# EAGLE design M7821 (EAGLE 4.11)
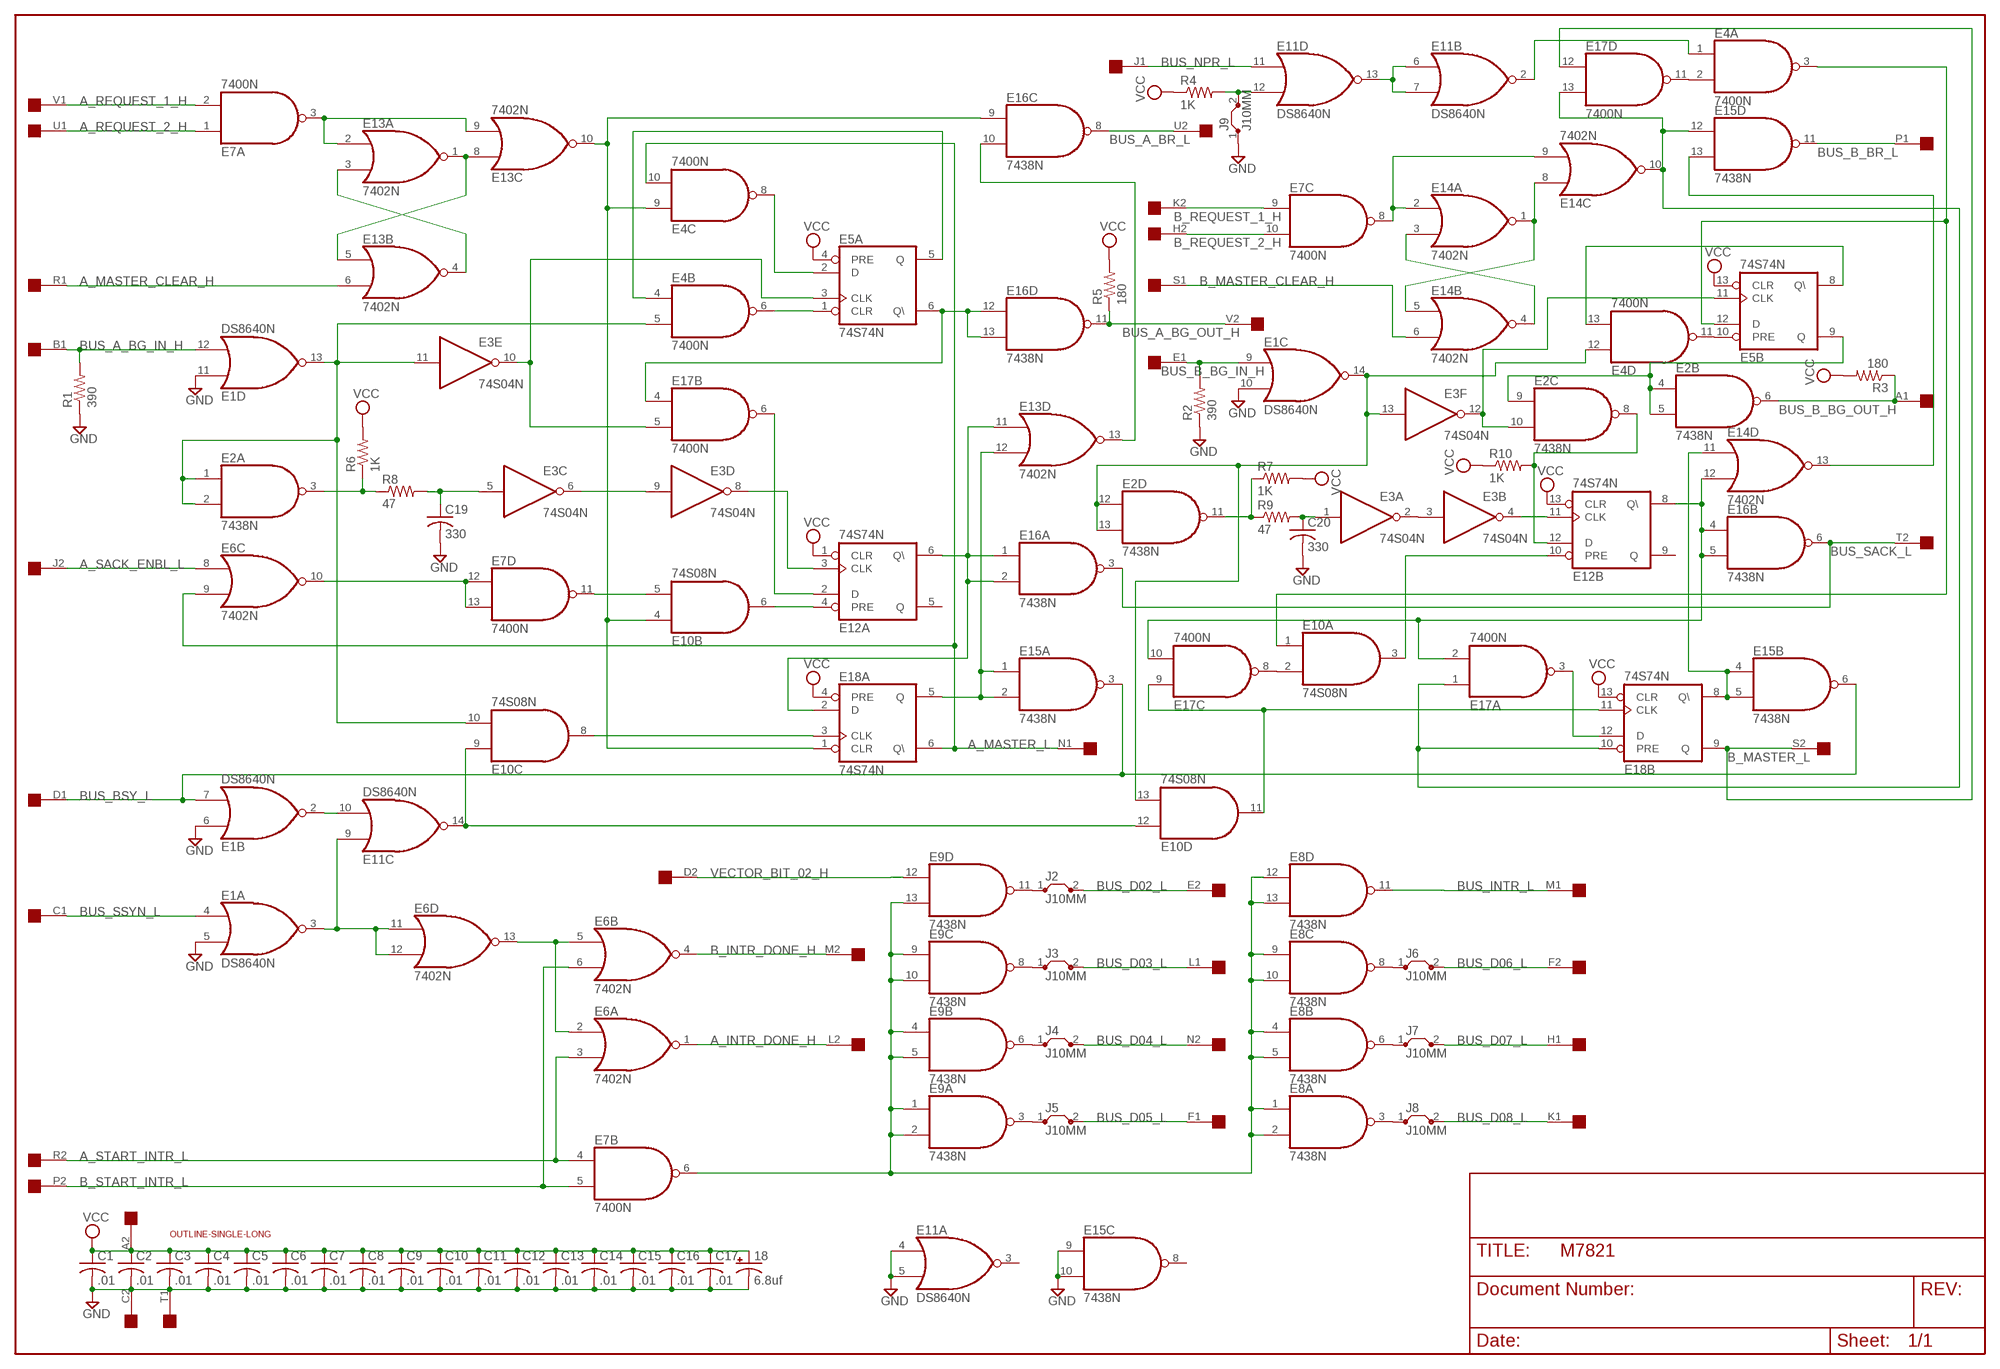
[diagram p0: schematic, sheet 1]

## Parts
18  6.8uf  CPOL-USE15-5AXIAL  [E15-5]
C1  .01  C-US050-025X075  [C050-025X075]
C2  .01  C-US050-025X075  [C050-025X075]
C3  .01  C-US050-025X075  [C050-025X075]
C4  .01  C-US050-025X075  [C050-025X075]
C5  .01  C-US050-025X075  [C050-025X075]
C6  .01  C-US050-025X075  [C050-025X075]
C7  .01  C-US050-025X075  [C050-025X075]
C8  .01  C-US050-025X075  [C050-025X075]
C9  .01  C-US050-025X075  [C050-025X075]
C10  .01  C-US050-025X075  [C050-025X075]
C11  .01  C-US050-025X075  [C050-025X075]
C12  .01  C-US050-025X075  [C050-025X075]
C13  .01  C-US050-025X075  [C050-025X075]
C14  .01  C-US050-025X075  [C050-025X075]
C15  .01  C-US050-025X075  [C050-025X075]
C16  .01  C-US050-025X075  [C050-025X075]
C17  .01  C-US050-025X075  [C050-025X075]
C19  330  C-US050-025X075  [C050-025X075]
C20  330  C-US050-025X075  [C050-025X075]
E1  DS8640N  [DIL14]
E2  7438N  [DIL14]
E3  74S04N  [DIL14]
E4  7400N  [DIL14]
E5  74S74N  [DIL14]
E6  7402N  [DIL14]
E7  7400N  [DIL14]
E8  7438N  [DIL14]
E9  7438N  [DIL14]
E10  74S08N  [DIL14]
E11  DS8640N  [DIL14]
E12  74S74N  [DIL14]
E13  7402N  [DIL14]
E14  7402N  [DIL14]
E15  7438N  [DIL14]
E16  7438N  [DIL14]
E17  7400N  [DIL14]
E18  74S74N  [DIL14]
J2  J10MM  [10]
J3  J10MM  [10]
J4  J10MM  [10]
J5  J10MM  [10]
J6  J10MM  [10]
J7  J10MM  [10]
J8  J10MM  [10]
J9  J10MM  [10]
R1  390  R-US_0207/10  [0207/10]
R2  390  R-US_0207/10  [0207/10]
R3  180  R-US_0207/10  [0207/10]
R4  1K  R-US_0207/10  [0207/10]
R5  180  R-US_0207/10  [0207/10]
R6  1K  R-US_0207/10  [0207/10]
R7  1K  R-US_0207/10  [0207/10]
R8  47  R-US_0207/10  [0207/10]
R9  47  R-US_0207/10  [0207/10]
R10  1K  R-US_0207/10  [0207/10]
U$1  OUTLINE-SINGLE-LONG  [SINGLE-LONG]
U$2  SINGLE  [EDGE-CON2]

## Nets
A_INTR_DONE_H: E6.1(A:O) U$2.L2
A_MASTER_CLEAR_H: E13.6(B:I1) U$2.R1
A_MASTER_L: E4.10(C:I1) E6.9(C:I1) E18.6(A:Q\) U$2.N1
A_REQUEST_1_H: E7.2(A:I1) U$2.V1
A_REQUEST_2_H: E7.1(A:I0) U$2.U1
A_SACK_ENBL_L: E6.8(C:I0) U$2.J2
A_START_INTR_L: E6.3(A:I1) E7.4(B:I0) U$2.R2
B_INTR_DONE_H: E6.4(B:O) U$2.M2
B_MASTER_CLEAR_H: E14.6(B:I1) U$2.S1
B_MASTER_L: E17.12(D:I0) E18.9(B:Q) U$2.S2
B_REQUEST_1_H: E7.9(C:I0) U$2.K2
B_REQUEST_2_H: E7.10(C:I1) U$2.H2
B_START_INTR_L: E6.6(B:I1) E7.5(B:I1) U$2.P2
BUS_A_BG_IN_H: E1.12(D:I1) R1.2 U$2.B1
BUS_A_BG_OUT_H: E16.11(D:O) R5.1 U$2.V2
BUS_A_BR_L: E16.8(C:O) U$2.U2
BUS_B_BG_IN_H: E1.9(C:I0) R2.2 U$2.E1
BUS_B_BG_OUT_H: E2.6(B:O) R3.1 U$2.A1
BUS_B_BR_L: E15.11(D:O) U$2.P1
BUS_BSY_L: E1.7(B:I1) E15.3(A:O) E15.6(B:O) U$2.D1
BUS_D02_L: J2.2 U$2.E2
BUS_D03_L: J3.2 U$2.L1
BUS_D04_L: J4.2 U$2.N2
BUS_D05_L: J5.2 U$2.F1
BUS_D06_L: J6.2 U$2.F2
BUS_D07_L: J7.2 U$2.H1
BUS_D08_L: J8.2 U$2.K1
BUS_INTR_L: E8.11(D:O) U$2.M1
BUS_NPR_L: E11.11(D:I0) U$2.J1
BUS_SACK_L: E16.3(A:O) E16.6(B:O) U$2.T2
BUS_SSYN_L: E1.4(A:I0) U$2.C1
GND: 18.- C1.2 C2.2 C3.2 C4.2 C5.2 C6.2 C7.2 C8.2 C9.2 C10.2 C11.2 C12.2 C13.2 C14.2 C15.2 C16.2 C17.2 C19.2 C20.2 E1.5(A:I1) E1.6(B:I0) E1.10(C:I1) E1.11(D:I0) E11.4(A:I0) E11.5(A:I1) E15.9(C:I0) E15.10(C:I1) J9.1 R1.1 R2.1 U$2.C2 U$2.T1
N$1: E1.14(C:O) E2.12(D:I0) E2.13(D:I1) E3.13(F:I) E4.12(D:I0) E10.13(D:I1)
N$2: E1.13(D:O) E2.1(A:I0) E2.2(A:I1) E3.11(E:I) E4.5(B:I1) E10.10(C:I1)
N$3: E1.3(A:O) E6.11(D:I0) E6.12(D:I1) E11.9(C:I0)
N$4: E1.2(B:O) E11.10(C:I1)
N$5: E7.8(C:O) E14.2(A:I0) E14.9(C:I1)
N$6: E11.12(D:I1) J9.2 R4.2
N$7: E11.6(B:I0) E11.7(B:I1) E11.13(D:O)
N$8: E6.10(C:O) E7.12(D:I0) E7.13(D:I1)
N$9: E14.3(A:I1) E14.4(B:O)
N$10: E9.11(D:O) J2.1
N$11: E3.8(D:O) E12.3(A:CLK)
N$12: E7.11(D:O) E10.5(B:I1)
N$13: E4.13(D:I1) E5.8(B:Q\)
N$14: E14.1(A:O) E14.5(B:I0) E14.8(C:I0)
N$15: E2.11(D:O) R7.1 R9.1
N$16: E9.3(A:O) J5.1
N$17: E9.6(B:O) J4.1
N$18: E9.8(C:O) J3.1
N$19: E10.9(C:I0) E10.12(D:I0) E11.14(C:O)
N$20: E8.3(A:O) J8.1
N$21: E8.6(B:O) J7.1
N$22: E8.8(C:O) J6.1
N$23: E7.6(B:O) E8.1(A:I0) E8.2(A:I1) E8.4(B:I0) E8.5(B:I1) E8.9(C:I0) E8.10(C:I1) E8.12(D:I0) E8.13(D:I1) E9.1(A:I0) E9.2(A:I1) E9.4(B:I0) E9.5(B:I1) E9.9(C:I0) E9.10(C:I1) E9.13(D:I1)
N$24: E12.6(A:Q\) E13.11(D:I0) E16.1(A:I0) E16.2(A:I1) E18.2(A:D)
N$25: E13.12(D:I1) E15.1(A:I0) E15.2(A:I1) E18.5(A:Q)
N$26: E4.6(B:O) E5.1(A:CLR)
N$27: E4.8(C:O) E5.2(A:D)
N$28: E4.4(B:I0) E5.5(A:Q)
N$29: E3.10(E:O) E5.3(A:CLK) E17.5(B:I1)
N$30: E12.2(A:D) E17.6(B:O)
N$31: E5.6(A:Q\) E16.12(D:I0) E16.13(D:I1) E17.4(B:I0)
N$32: E13.13(D:O) E16.10(C:I1)
N$33: C20.1 E3.1(A:I) R9.2
N$34: E6.2(A:I0) E6.5(B:I0) E6.13(D:O)
N$35: E3.2(A:O) E3.3(B:I)
N$36: E3.4(B:O) E12.11(B:CLK)
N$37: E10.6(B:O) E12.4(A:PRE)
N$38: E2.3(A:O) R6.1 R8.1
N$39: C19.1 E3.5(C:I) R8.2
N$40: E3.6(C:O) E3.9(D:I)
N$41: E10.11(D:O) E17.9(C:I0) E18.11(B:CLK)
N$42: E7.3(A:O) E13.2(A:I0) E13.9(C:I1)
N$43: E13.1(A:O) E13.5(B:I0) E13.8(C:I0)
N$44: E13.3(A:I1) E13.4(B:O)
N$45: E4.9(C:I0) E10.4(B:I0) E13.10(C:O) E16.9(C:I0) E18.1(A:CLR)
N$46: E10.8(C:O) E18.3(A:CLK)
N$47: E4.1(A:I0) E11.2(B:O)
N$48: E14.11(D:I0) E15.4(B:I0) E15.5(B:I1) E18.8(B:Q\)
N$49: E17.3(A:O) E18.12(B:D)
N$50: E14.10(C:O) E15.12(D:I0) E17.1(A:I0) E17.13(D:I1) E18.10(B:PRE)
N$51: E10.2(A:I1) E17.8(C:O)
N$52: E12.8(B:Q\) E14.12(D:I1) E16.4(B:I0) E16.5(B:I1) E17.2(A:I1) E17.10(C:I1)
N$53: E10.3(A:O) E12.10(B:PRE)
N$54: E4.3(A:O) E5.12(B:D) E10.1(A:I0)
N$55: E2.8(C:O) E12.12(B:D) R10.2
N$56: E2.10(C:I1) E3.12(F:O) E5.11(B:CLK)
N$57: E2.4(B:I0) E2.5(B:I1) E2.9(C:I0) E5.9(B:Q)
N$58: E4.11(D:O) E5.10(B:PRE)
N$60: E4.2(A:I1) E17.11(D:O)
N$61: E14.13(D:O) E15.13(D:I1)
VCC: 18.+ C1.1 C2.1 C3.1 C4.1 C5.1 C6.1 C7.1 C8.1 C9.1 C10.1 C11.1 C12.1 C13.1 C14.1 C15.1 C16.1 C17.1 E5.4(A:PRE) E5.13(B:CLR) E12.1(A:CLR) E12.13(B:CLR) E18.4(A:PRE) E18.13(B:CLR) R3.2 R4.1 R5.2 R6.2 R7.2 R10.1 U$2.A2
VECTOR_BIT_02_H: E9.12(D:I0) U$2.D2
Unconnected: E11.3(A:O) E12.5(A:Q) E12.9(B:Q) E15.8(C:O) U$2.B2

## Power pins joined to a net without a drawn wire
GND: E1.1(P:GND) E2.7(P:GND) E3.7(P:GND) E4.7(P:GND) E5.7(P:GND) E6.7(P:GND) E7.7(P:GND) E8.7(P:GND) E9.7(P:GND) E10.7(P:GND) E11.1(P:GND) E12.7(P:GND) E13.7(P:GND) E14.7(P:GND) E15.7(P:GND) E16.7(P:GND) E17.7(P:GND) E18.7(P:GND)
VCC: E1.8(P:VCC) E2.14(P:VCC) E3.14(P:VCC) E4.14(P:VCC) E5.14(P:VCC) E6.14(P:VCC) E7.14(P:VCC) E8.14(P:VCC) E9.14(P:VCC) E10.14(P:VCC) E11.8(P:VCC) E12.14(P:VCC) E13.14(P:VCC) E14.14(P:VCC) E15.14(P:VCC) E16.14(P:VCC) E17.14(P:VCC) E18.14(P:VCC)

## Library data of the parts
18 = rcl:CPOL-US: POLARIZED CAPACITOR, American symbol
C1-C17 C19 C20 = rcl:C-US: CAPACITOR, American symbol
E1 E11 = dec-con:DS8640: Quad NOR gate
E2 E8 E9 E15 E16 = 74xx-jameco:74*38: Quad 2-input NAND gate, open collector output
E3 = 74xx-jameco:74*04: Hex INVERTER
E4 E7 E17 = 74xx-jameco:74*00: Quad 2-input NAND gate
E5 E12 E18 = 74xx-jameco:74*74: Dual D type positive edge triggered FLIP FLOP, preset and clear
E6 E14 = 74xx-jameco:74*02: Quad 2-input NOR gate
E10 = 74xx-jameco:74*08: Quad 2-input AND gate
E13 = 74xx-us:74*02: Quad 2-input NOR gate
J2-J9 = jumper:J: Bridge
R1-R10 = rcl:R-US_: RESISTOR, American symbol
U$1 = dec-con:OUTLINE-*: Board outlines for DEC boards.
U$2 = dec-con:SINGLE: Single-Height DEC board

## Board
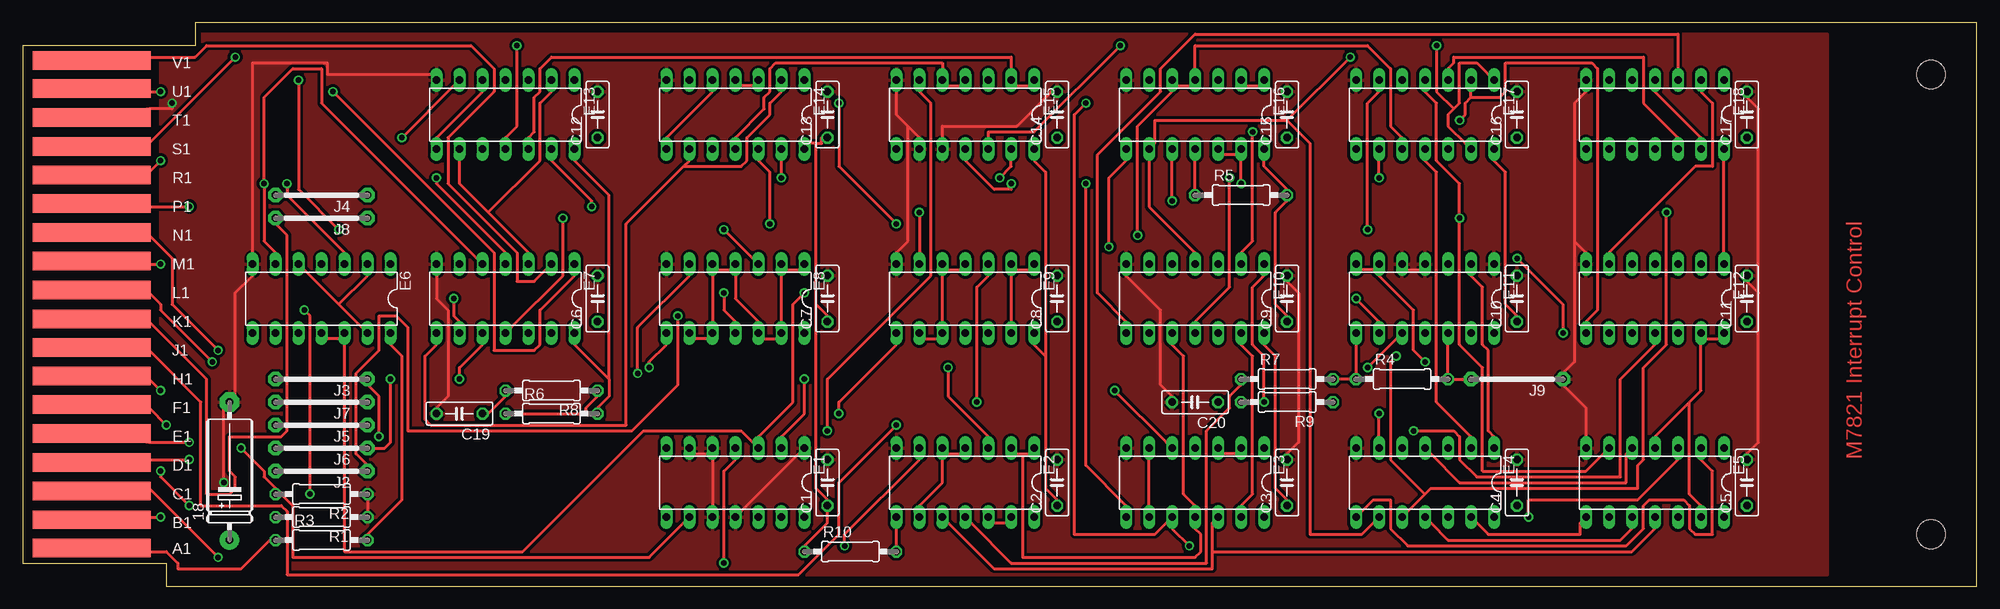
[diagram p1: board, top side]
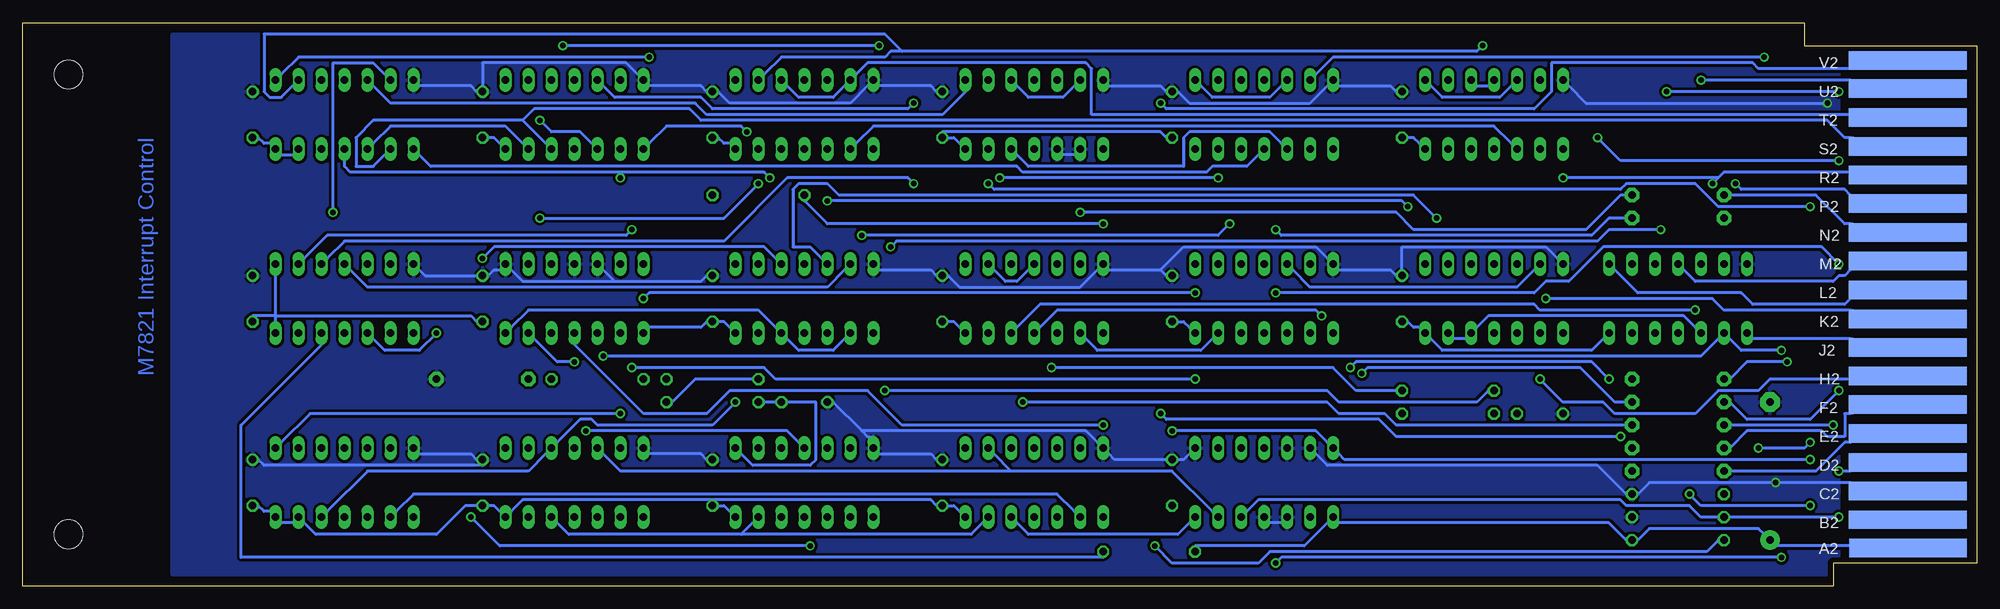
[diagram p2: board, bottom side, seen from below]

Size 215.9 x 62.23 mm. Coordinates in mm from the lower left corner, seen from the top.
Copper layers (1*16): Top 0.035mm / dielectric 1.5mm / Bottom 0.035mm
Design rules "15mils": minimum track width 13mil, minimum drill 24mil, track to track 12mil, track to pad 10mil, pad to pad 10mil, via to via 10mil, smd to smd 10mil, copper to edge 25mil, drill to drill 10mil, minimum pad ring 10mil, minimum via ring 8mil, stop-mask expansion 0mil, vias tented up to drill 0mil, thermal gap 10mil

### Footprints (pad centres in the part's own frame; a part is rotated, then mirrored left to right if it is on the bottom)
E15-5 = drill 0.813 pad 2.159 round: + -7.62,0 | drill 0.813 pad 2.159 octagon: - 7.62,0
C050-025X075 = drill 0.813 octagon: 1 -2.54,0; 2 2.54,0
DIL14 = drill 0.813 long: 1 -7.62,-3.81; 2 -5.08,-3.81; 3 -2.54,-3.81; 4 0,-3.81; 5 2.54,-3.81; 6 5.08,-3.81; 7 7.62,-3.81; 8 7.62,3.81; 9 5.08,3.81; 10 2.54,3.81; 11 0,3.81; 12 -2.54,3.81; 13 -5.08,3.81; 14 -7.62,3.81
10 = drill 0.813 pad 1.6 octagon: 1 -5.08,0; 2 5.08,0
0207/10 = drill 0.813 octagon: 1 -5.08,0; 2 5.08,0
SINGLE-LONG = hole 3.175: 210.82,56.515; 210.82,5.715
EDGE-CON2 = smd 13.017 x 2.032: A1 7.633,4.207; B1 7.639,7.327; C1 7.636,10.489; D1 7.633,13.665; E1 7.642,16.84; F1 7.642,20.041; H1 7.642,23.19; J1 7.642,26.34; K1 7.642,29.515; L1 7.642,32.69; M1 7.642,35.89; N1 7.642,39.04; P1 7.642,42.24; R1 7.642,45.39; S1 7.642,48.565; T1 7.642,51.74; U1 7.642,54.966; V1 7.642,58.026 | smd 13.017 x 2.032 bottom: A2 7.614,4.207; B2 7.642,7.328; C2 7.617,10.49; D2 7.642,13.665; E2 7.642,16.84; F2 7.617,20.041; H2 7.617,23.19; J2 7.642,26.34; K2 7.642,29.515; L2 7.642,32.69; M2 7.642,35.89; N2 7.642,39.04; P2 7.642,42.24; R2 7.642,45.39; S2 7.642,48.565; T2 7.642,51.74; U2 7.642,54.966; V2 7.642,58.026

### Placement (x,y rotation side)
18  22.86,12.7 90 top
C1  88.9,11.43 90 top
C2  114.3,11.43 90 top
C3  139.7,11.43 90 top
C4  165.1,11.43 90 top
C5  190.5,11.43 90 top
C6  63.5,31.75 90 top
C7  88.9,31.75 90 top
C8  114.3,31.75 90 top
C9  139.7,31.75 90 top
C10  165.1,31.75 90 top
C11  190.5,31.75 90 top
C12  63.5,52.07 90 top
C13  88.9,52.07 90 top
C14  114.3,52.07 90 top
C15  139.7,52.07 90 top
C16  165.1,52.07 90 top
C17  190.5,52.07 90 top
C19  48.26,19.05 180 top
C20  129.54,20.32 180 top
E1  78.74,11.43 180 top
E2  104.14,11.43 180 top
E3  129.54,11.43 180 top
E4  154.94,11.43 180 top
E5  180.34,11.43 180 top
E6  33.02,31.75 180 top
E7  53.34,31.75 180 top
E8  78.74,31.75 180 top
E9  104.14,31.75 180 top
E10  129.54,31.75 180 top
E11  154.94,31.75 180 top
E12  180.34,31.75 180 top
E13  53.34,52.07 180 top
E14  78.74,52.07 180 top
E15  104.14,52.07 180 top
E16  129.54,52.07 180 top
E17  154.94,52.07 180 top
E18  180.34,52.07 180 top
J2  33.02,12.7 180 top
J3  33.02,22.86 180 top
J4  33.02,43.18 180 top
J5  33.02,17.78 180 top
J6  33.02,15.24 180 top
J7  33.02,20.32 180 top
J8  33.02,40.64 180 top
J9  165.1,22.86 180 top
R1  33.02,7.62 180 top
R2  33.02,10.16 180 top
R3  33.02,5.08 0 top
R4  152.4,22.86 0 top
R5  134.62,43.18 0 top
R6  58.42,19.05 0 top
R7  139.7,22.86 0 top
R8  58.42,21.59 180 top
R9  139.7,20.32 180 top
R10  91.44,3.81 0 top
U$1  0,0 0 top
U$2  0,0 0 top

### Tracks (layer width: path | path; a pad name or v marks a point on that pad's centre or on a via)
A_INTR_DONE_H
  Bottom 0.33: E6.1 40.01,34.92 37.47,32.38 26.04,32.38 24.77,31.11 14.61,31.11 13.97,31.75 U$2.L2
A_MASTER_CLEAR_H  (via drill 0.61)
  Top 0.33: v41.91,49.53 47.63,55.24 E13.6 | v15.24,46.99 13.97,45.72 U$2.R1
  Bottom 0.33: v41.91,49.53 39.37,46.99 v15.24,46.99
A_MASTER_L  (via drill 0.61)
  Top 0.33: v21.59,26.04 16.51,31.11 16.51,36.2 13.97,38.73 U$2.N1 | 154.94,10.16 155.58,10.79 178.44,10.79 178.44,13.34 179.07,13.97 179.07,24.13 181.61,26.67 v181.61,41.27 | 154.94,10.16 153.04,8.26 E4.10 | v151.77,25.4 151.13,24.77 151.13,13.97 154.94,10.16
  Bottom 0.33: v21.59,26.04 26.04,26.04 27.31,27.3 E6.9 28.58,27.3 30.48,25.4 v151.77,25.4 | v181.61,41.27 181.61,57.78 177.17,57.78 175.9,56.52 E18.6
A_REQUEST_1_H
  Top 0.33: E7.2 57.79,34.92 56.52,33.66 54.61,33.66 54.61,36.83 46.99,44.45 46.99,49.53 52.07,54.61 52.07,57.15 49.53,59.69 20.32,59.69 19.05,58.42 13.97,58.42 U$2.V1
A_REQUEST_2_H  (via drill 0.61)
  Top 0.33: v34.29,54.61 52.07,36.83 52.07,26.04 56.52,26.04 57.15,26.67 57.15,30.48 60.96,34.29 E7.1 | v15.24,54.61 13.97,54.61 U$2.U1
  Bottom 0.33: v15.24,54.61 v34.29,54.61
A_SACK_ENBL_L
  Bottom 0.33: E6.8 24.77,27.3 13.97,27.3 U$2.J2
A_START_INTR_L  (via drill 0.61)
  Top 0.33: v29.21,44.45 29.21,43.18 35.56,36.83 E6.3 | v45.72,45.09 45.72,44.45 53.34,36.83 E7.4
  Bottom 0.33: 28.58,45.09 27.94,45.72 13.97,45.72 U$2.R2 | 28.58,45.09 v29.21,44.45 | 28.58,45.09 v45.72,45.09
B_INTR_DONE_H
  Bottom 0.33: E6.4 32.39,34.92 31.12,33.66 15.88,33.66 15.24,34.29 14.61,34.29 13.97,34.92 U$2.M2
B_MASTER_CLEAR_H  (via drill 0.61)
  Top 0.33: v23.5,58.42 13.97,48.9 U$2.S1
  Bottom 0.33: v23.5,58.42 71.12,58.42 73.03,56.52 E14.6
B_MASTER_L
  Bottom 0.33: 160.66,51.44 158.12,48.9 E17.12 | 160.66,51.44 177.17,51.44 179.07,49.53 179.07,46.35 177.17,46.35 175.9,47.62 E18.9 | 160.66,51.44 159.39,52.7 142.24,52.7 140.97,51.44 16.51,51.44 14.61,49.53 13.97,49.53 U$2.S2
B_REQUEST_1_H  (via drill 0.61)
  Top 0.33: v47.63,31.75 47.63,29.84 48.26,29.21 E7.9
  Bottom 0.33: v47.63,31.75 29.21,31.75 27.94,30.48 13.97,30.48 U$2.K2
B_REQUEST_2_H  (via drill 0.61)
  Top 0.33: v48.26,22.86 48.26,24.13 50.8,26.67 E7.10
  Bottom 0.33: v48.26,22.86 45.72,20.32 41.28,20.32 40.01,19.05 31.12,19.05 28.58,21.59 24.13,21.59 22.86,22.86 13.97,22.86 U$2.H2
B_START_INTR_L  (via drill 0.61)
  Top 0.33: E6.6 27.94,36.83 26.67,38.1 v26.67,44.45 26.67,53.98 29.85,57.15 33.02,57.15 33.02,53.34 50.17,36.2 E7.5
  Bottom 0.33: v26.67,44.45 26.04,43.81 14.61,43.81 13.97,43.18 U$2.P2
BUS_A_BG_IN_H  (via drill 0.61)
  Top 0.33: v15.24,7.62 13.97,7.62 U$2.B1
  Bottom 0.33: v15.24,7.62 27.31,7.62 R1.2 28.58,7.62 30.48,7.62 31.75,8.89 38.74,8.89 39.37,9.53 79.38,9.53 80.65,8.26 E1.12
BUS_A_BG_OUT_H  (via drill 0.61)
  Top 0.33: R5.1 129.54,43.81 129.54,46.99 E16.11 | v96.52,40.01 90.17,46.35 v90.17,53.34
  Bottom 0.33: v96.52,40.01 127,40.01 129.54,42.55 R5.1 | v90.17,53.34 89.54,52.7 48.9,52.7 46.99,54.61 46.99,57.78 24.77,57.78 24.13,57.15 13.97,57.15 U$2.V2
BUS_A_BR_L  (via drill 0.61)
  Top 0.33: v120.02,37.47 120.02,45.09 121.92,46.99 E16.8 | v34.93,39.37 30.48,43.81 v30.48,55.88
  Bottom 0.33: v120.02,37.47 119.38,38.1 41.91,38.1 40.64,39.37 v34.93,39.37 | v30.48,55.88 13.97,55.88 U$2.U2
BUS_B_BG_IN_H  (via drill 0.61)
  Top 0.33: E1.9 73.03,6.99 69.22,3.17 29.85,3.17 29.85,8.89 28.58,10.16 R2.2 27.94,10.79 26.67,12.06 26.67,12.7 v24.13,15.24 | v18.42,15.88 13.97,15.88 U$2.E1
  Bottom 0.33: v18.42,15.88 19.05,15.24 v24.13,15.24
BUS_B_BG_OUT_H  (via drill 0.61)
  Top 0.33: R3.1 27.31,5.08 24.13,1.91 17.15,1.91 17.15,2.54 15.88,3.81 13.97,3.81 U$2.A1 | v90.81,4.45 90.81,5.71 99.06,13.97 E2.6
  Bottom 0.33: v90.81,4.45 88.9,2.54 79.38,2.54 78.11,3.81 29.85,3.81 28.58,5.08 R3.1
BUS_B_BR_L  (via drill 0.61)
  Top 0.33: v109.22,44.45 109.22,43.81 107.32,43.81 104.14,46.99 E15.11 | v18.42,41.91 13.97,41.91 U$2.P1
  Bottom 0.33: v109.22,44.45 108.59,43.81 39.37,43.81 38.74,44.45 31.12,44.45 28.58,41.91 v18.42,41.91
BUS_BSY_L  (via drill 0.61)
  Top 0.33: v18.42,13.97 13.97,13.97 U$2.D1 | v88.9,17.14 88.9,22.86 100.33,34.29 100.33,53.34 99.06,54.61 E15.6
  Bottom 0.33: E15.6 99.7,55.24 100.97,53.98 104.78,53.98 106.05,55.24 E15.3 | v18.42,13.97 69.85,13.97 70.49,14.61 E1.7 71.76,15.88 73.03,17.14 v88.9,17.14
BUS_D02_L
  Bottom 0.33: J2.2 27.31,12.7 17.78,12.7 14.61,15.88 13.97,15.88 U$2.E2
BUS_D03_L  (via drill 0.61)
  Top 0.33: v20.96,24.77 15.24,30.48 15.24,31.11 13.97,32.38 U$2.L1
  Bottom 0.33: v20.96,24.77 25.4,24.77 27.31,22.86 J3.2
BUS_D04_L
  Bottom 0.33: J4.2 27.31,43.18 17.78,43.18 14.61,40.01 13.97,40.01 U$2.N2
BUS_D05_L  (via drill 0.61)
  Top 0.33: v15.88,17.78 13.97,19.68 U$2.F1
  Bottom 0.33: v15.88,17.78 27.31,17.78 J5.2
BUS_D06_L
  Bottom 0.33: J6.2 27.31,15.24 25.4,17.14 17.15,17.14 16.51,16.51 14.61,16.51 14.61,19.05 13.97,19.05 U$2.F2
BUS_D07_L  (via drill 0.61)
  Top 0.33: v15.24,21.59 13.97,22.86 U$2.H1
  Bottom 0.33: v15.24,21.59 18.42,18.41 25.4,18.41 27.31,20.32 J7.2
BUS_D08_L
  Top 0.33: J8.2 27.94,40.01 29.21,38.73 29.21,17.14 28.58,16.51 22.86,16.51 22.86,12.7 23.5,12.06 23.5,10.79 22.86,10.16 20.32,10.16 20.32,22.86 13.97,29.21 U$2.K1
BUS_INTR_L  (via drill 0.61)
  Top 0.33: v77.47,32.38 77.47,30.48 78.74,29.21 E8.11 | v15.24,35.56 13.97,35.56 U$2.M1
  Bottom 0.33: v77.47,32.38 48.9,32.38 47.63,33.66 45.09,33.66 41.28,37.47 17.15,37.47 v15.24,35.56
BUS_NPR_L  (via drill 0.61)
  Top 0.33: v96.52,17.78 90.17,11.43 90.17,5.71 85.73,1.27 29.21,1.27 29.21,8.26 28.58,8.89 19.69,8.89 19.69,20.32 13.97,26.04 U$2.J1
  Bottom 0.33: v96.52,17.78 118.75,17.78 122.56,21.59 137.8,21.59 140.34,19.05 147.32,19.05 154.94,26.67 E11.11
BUS_SACK_L
  Bottom 0.33: E16.3 131.45,55.24 130.18,53.98 126.37,53.98 125.1,55.24 E16.6 123.83,56.52 122.56,57.78 98.43,57.78 97.79,57.15 97.79,52.07 13.97,52.07 U$2.T2
BUS_SSYN_L  (via drill 0.61)
  Top 0.33: v77.47,2.54 77.47,12.7 78.74,13.97 E1.4 | v21.59,3.17 13.97,10.79 U$2.C1
  Bottom 0.33: v77.47,2.54 76.84,3.17 v21.59,3.17
GND  (via drill 0.61)
  Top 0.33: E13.7 45.09,56.52 33.66,56.52 33.66,57.78 25.4,57.78 25.4,36.83 E6.7 25.4,34.29 23.5,32.38 23.5,20.95 18.- 22.23,19.68 v22.23,11.43 | v16.51,53.34 16.51,52.7 13.97,52.7 U$2.T1 | R1.1 38.1,8.26 38.1,9.53 R2.1 | E1.6 74.3,14.61 75.57,14.61 E1.5 76.2,13.97 76.2,8.89 E1.10 | E1.1 85.73,14.61 79.38,8.26 E1.11 | E10.7 121.92,34.29 125.73,30.48 125.73,22.23 127,20.95 C20.2 | 191.77,32.38 190.5,33.66 C11.2 | 191.77,32.38 191.77,15.88 190.5,14.61 C5.2 | 191.77,32.38 191.77,52.7 190.5,53.98 C17.2 | E5.7 172.72,16.51 172.72,19.68 170.18,22.23 J9.1 170.18,23.5 171.45,24.77 171.45,38.1 | 171.45,38.1 171.45,53.34 172.72,54.61 E18.7 | 171.45,38.1 172.72,36.83 E12.7 | E11.4 154.31,34.92 153.04,34.92 E11.5 | C3.2 139.7,14.61 140.97,15.88 140.97,32.38 139.7,33.66 C9.2 | C19.2 45.72,19.68 46.99,20.95 46.99,30.48 45.72,31.75 45.72,34.29 E7.7 | 97.79,50.8 96.52,52.07 96.52,54.61 E15.7 | 97.79,50.8 99.06,49.53 E15.9 | 97.79,50.8 97.79,38.1 96.52,36.83 E9.7 | C14.2 113.67,54.61 109.86,50.8 101.6,50.8 101.6,49.53 E15.10
  Bottom 0.33: v16.51,53.34 43.18,53.34 45.09,55.24 E13.7 | U$2.C2 13.97,11.43 v22.23,11.43 36.2,11.43 37.47,10.16 R2.1 38.74,10.16 41.91,13.34 71.76,13.34 73.03,14.61 E1.6 | E1.1 87,14.61 87.63,13.97 88.27,13.97 C1.2 89.54,13.97 95.25,13.97 95.89,14.61 E2.7 97.16,15.88 98.43,17.14 123.19,17.14 | E1.10 76.84,6.99 78.11,6.99 E1.11 | E10.7 121.29,34.92 115.57,34.92 114.94,34.29 C8.2 113.67,34.29 112.4,33.02 99.06,33.02 97.16,34.92 E9.7 95.89,34.92 90.17,34.92 | C2.2 114.94,13.97 115.57,14.61 121.29,14.61 E3.7 121.92,16.51 122.56,16.51 123.19,17.14 | 123.19,17.14 126.37,20.32 C20.2 | E5.7 172.09,14.61 166.37,14.61 165.74,13.97 C4.2 165.1,13.34 189.23,13.34 189.87,13.97 C5.2 | E18.7 172.09,55.24 166.37,55.24 165.74,54.61 C16.2 165.1,55.24 165.1,57.78 149.23,57.78 147.96,56.52 E17.7 146.69,55.24 140.97,55.24 140.34,54.61 C15.2 139.07,54.61 137.8,53.34 124.46,53.34 122.56,55.24 E16.7 121.29,55.24 115.57,55.24 114.94,54.61 C14.2 | E12.7 172.09,34.92 171.45,34.29 165.74,34.29 C10.2 164.47,34.29 163.83,34.92 163.2,34.92 E11.1 161.93,34.92 160.66,33.66 150.5,33.66 | C3.2 140.34,13.97 140.97,14.61 146.69,14.61 E4.7 | 150.5,33.66 140.97,33.66 140.34,34.29 C9.2 | 150.5,33.66 151.77,34.92 E11.5 | E7.7 46.36,36.2 47.63,37.47 63.5,37.47 63.5,34.92 C6.2 64.14,34.29 64.77,34.92 70.49,34.92 E8.7 71.76,36.2 73.03,37.47 87.63,37.47 90.17,34.92 | C12.2 64.14,54.61 64.77,55.24 70.49,55.24 E14.7 71.76,55.24 73.66,53.34 87,53.34 88.27,54.61 C13.2 89.54,54.61 90.17,55.24 95.89,55.24 E15.7 | 90.17,34.92 89.54,34.29 C7.2 | E15.9 99.7,47.62 100.97,47.62 E15.10
  pour Bottom: 15.24,60.96 199.39,60.96 199.39,1.27 15.24,1.27
  pour Top: 15.24,60.96 199.39,60.96 199.39,1.27 15.24,1.27
N$1
  Top 0.33: E2.13 108.59,6.99 107.32,6.99 E2.12 | E3.13 134.62,8.89 135.89,10.16 135.89,25.4 134.62,26.67 E10.13
  Bottom 0.33: E1.14 87,6.99 88.27,5.71 104.78,5.71 106.05,6.99 E2.12 | 136.53,5.71 155.58,5.71 156.85,6.99 E4.12 | 136.53,5.71 135.26,6.99 E3.13 | 136.53,5.71 111.13,5.71 109.86,6.99 E2.13
N$2
  Top 0.33: E10.10 127,26.67 128.27,25.4 128.27,10.16 129.54,8.89 E3.11 129.54,6.35 130.18,5.71 130.18,3.81 129.54,3.17 110.49,3.17 110.49,14.61 | 110.49,14.61 109.86,14.61 E2.2 | 110.49,14.61 111.13,14.61 E2.1
  Bottom 0.33: 106.68,12.7 88.9,12.7 84.46,8.26 E1.13 | 106.68,12.7 108.59,14.61 E2.2 | 106.68,12.7 149.86,12.7 151.77,14.61 E4.5
N$3  (via drill 0.61)
  Top 0.33: E6.11 33.66,27.3 34.93,27.3 E6.12 35.56,26.67 35.56,3.81 55.25,3.81 68.58,17.14 79.38,17.14 80.65,15.88 E1.3 81.28,16.51 85.09,20.32 85.09,31.11 v86.36,32.38 | v147.32,31.75 149.86,29.21 E11.9
  Bottom 0.33: v147.32,31.75 146.69,32.38 v86.36,32.38
N$4  (via drill 0.61)
  Top 0.33: v86.36,22.86 86.36,19.05 83.82,16.51 E1.2 | v148.59,24.13 151.77,27.3 E11.10
  Bottom 0.33: v86.36,22.86 132.72,22.86 133.99,24.13 v148.59,24.13
N$5
  Top 0.33: 73.03,46.35 73.66,46.99 E14.9 | 73.03,46.35 66.68,40.01 66.68,17.78 45.09,17.78 44.45,18.41 44.45,25.4 45.72,26.67 E7.8 | 73.03,46.35 79.38,46.35 80.01,46.99 80.01,49.53 82.55,52.07 82.55,53.34 83.82,54.61 E14.2
N$6
  Top 0.33: J9.2 159.39,22.86 158.12,22.86 R4.2 157.48,23.5 157.48,26.67 E11.12
N$7  (via drill 0.61)
  Top 0.33: E11.7 147.96,34.92 149.23,34.92 E11.6 149.86,34.29 153.67,30.48 153.67,26.04 v154.94,24.77
  Bottom 0.33: v154.94,24.77 156.85,24.77 159.39,27.3 E11.13
N$8
  Bottom 0.33: E6.10 31.12,28.57 32.39,29.84 53.98,29.84 55.25,28.57 E7.12 56.52,27.3 57.79,27.3 E7.13
N$9
  Top 0.33: E14.4 79.38,55.24 80.65,55.24 E14.3
N$10  (via drill 0.61)
  Top 0.33: v72.39,29.84 72.39,22.23 67.31,17.14 42.55,17.14 42.55,28.57 41.28,29.84 39.37,29.84 39.37,26.04 36.83,23.5 36.83,14.61 38.1,13.34 J2.1
  Bottom 0.33: v72.39,29.84 73.03,30.48 101.6,30.48 103.51,28.57 E9.11
N$11  (via drill 0.61)
  Top 0.33: v117.48,44.45 117.48,13.34 121.92,8.89 E3.8
  Bottom 0.33: v117.48,44.45 118.11,45.09 131.45,45.09 138.43,38.1 180.34,38.1 182.25,36.2 E12.3
N$12  (via drill 0.61)
  Top 0.33: v59.69,40.64 59.69,34.29 53.98,28.57 E7.11
  Bottom 0.33: v59.69,40.64 62.23,43.18 125.73,43.18 127,44.45 130.18,44.45 130.81,43.81 130.81,37.47 128.91,37.47 127.64,36.2 E10.5
N$13
  Top 0.33: E4.13 160.66,6.99 161.93,5.71 172.09,5.71 172.09,6.99 E5.8
N$14
  Top 0.33: E14.8 71.12,49.53 76.2,54.61 E14.5
  Bottom 0.33: E14.1 85.73,55.24 84.46,53.98 78.11,53.98 76.84,55.24 E14.5
N$15
  Top 0.33: E2.11 104.78,6.99 109.22,2.54 130.81,2.54 130.81,17.14 133.35,19.68 133.35,20.95 134.62,22.23 R7.1
  Bottom 0.33: R9.1 144.15,20.32 141.61,22.86 135.26,22.86 R7.1
N$16  (via drill 0.61)
  Top 0.33: v105.41,20.32 105.41,33.02 106.68,34.29 E9.3
  Bottom 0.33: v105.41,20.32 71.76,20.32 70.49,19.05 65.41,19.05 64.14,17.78 38.74,17.78 J5.1
N$17  (via drill 0.61)
  Top 0.33: v99.06,41.27 99.06,36.83 E9.6
  Bottom 0.33: v99.06,41.27 64.14,41.27 62.23,39.37 43.18,39.37 39.37,43.18 38.74,43.18 J4.1
N$18  (via drill 0.61)
  Top 0.33: v90.17,19.05 90.17,20.32 96.52,26.67 E9.8 | v39.37,16.51 39.37,20.95 38.1,22.23 J3.1
  Bottom 0.33: v90.17,19.05 89.54,18.41 66.04,18.41 64.14,16.51 v39.37,16.51
N$19
  Bottom 0.33: E10.9 125.1,27.3 126.37,26.04 130.18,26.04 131.45,27.3 E10.12 132.72,28.57 134.62,30.48 160.02,30.48 161.93,28.57 E11.14
N$20  (via drill 0.61)
  Top 0.33: v77.47,39.37 80.65,36.2 E8.3
  Bottom 0.33: v77.47,39.37 76.84,38.73 42.55,38.73 40.64,40.64 38.74,40.64 J8.1
N$21  (via drill 0.61)
  Top 0.33: v67.95,23.5 67.95,28.57 73.66,34.29 E8.6
  Bottom 0.33: v67.95,23.5 67.31,24.13 43.82,24.13 40.01,20.32 38.74,20.32 J7.1
N$22  (via drill 0.61)
  Top 0.33: v69.22,24.13 69.22,24.77 71.12,26.67 E8.8 | v40.64,22.86 40.64,15.88 40.01,15.24 38.74,15.24 J6.1
  Bottom 0.33: v69.22,24.13 68.58,24.77 42.55,24.77 v40.64,22.86
N$23
  Top 0.33: E9.13 109.22,29.21 109.22,34.29 E9.2 109.86,34.92 111.13,34.92 E9.1 | E9.9 99.7,27.3 100.97,27.3 E9.10 101.6,29.21 101.6,34.29 E9.5 102.24,34.92 103.51,34.92 E9.4 | E8.1 85.73,34.92 84.46,34.92 E8.2 83.82,34.29 83.82,29.21 E8.13 83.19,27.3 81.92,27.3 E8.12 81.28,29.21 78.74,31.75 78.74,34.29 E8.4 78.11,34.92 76.84,34.92 E8.5 76.2,34.29 76.2,29.21 E8.10 75.57,27.3 74.3,27.3 E8.9
  Bottom 0.33: E9.2 108.59,34.92 107.32,33.66 106.05,33.66 104.78,34.92 E9.4 | E7.6 48.9,34.92 50.8,33.02 73.66,33.02 75.57,34.92 E8.5 | E9.9 98.43,27.3 97.16,26.04 85.73,26.04 84.46,27.3 E8.13
N$24  (via drill 0.61)
  Top 0.33: E12.6 175.26,36.83 184.79,46.35 186.69,46.35 186.69,53.34 185.42,54.61 E18.2 | v54.61,59.69 54.61,50.8 53.34,49.53 E13.11 | E16.1 136.53,55.24 135.26,55.24 E16.2
  Bottom 0.33: v54.61,59.69 55.25,59.05 118.75,59.05 | 118.75,59.05 120.02,59.05 120.65,58.42 132.08,58.42 133.99,56.52 E16.2 | 118.75,59.05 120.65,60.96 189.23,60.96 189.23,54.61 188.6,53.98 187.33,53.98 186.06,55.24 E18.2
N$25
  Top 0.33: E13.12 55.88,49.53 56.52,50.16 56.52,53.98 57.15,54.61 57.15,57.15 58.42,58.42 109.22,58.42 109.22,57.15 E15.2 109.86,55.24 111.13,55.24 E15.1
  Bottom 0.33: E18.5 177.17,55.24 175.26,53.34 141.61,53.34 140.34,52.07 114.3,52.07 111.76,54.61 E15.1
N$26  (via drill 0.61)
  Top 0.33: v149.86,19.05 149.86,16.51 E4.6
  Bottom 0.33: v149.86,19.05 184.15,19.05 187.33,15.88 E5.1
N$27
  Top 0.33: E4.8 147.96,8.26 149.23,9.53 151.13,9.53 151.13,6.35 153.04,4.45 177.17,4.45 179.07,6.35 179.07,8.89 179.71,9.53 183.52,9.53 184.15,8.89 184.15,6.35 184.79,5.71 186.69,5.71 186.69,12.7 185.42,13.97 E5.2
N$28
  Top 0.33: E4.4 155.58,14.61 158.75,11.43 177.17,11.43 177.17,14.61 E5.5
N$29  (via drill 0.61)
  Top 0.33: v117.48,53.34 116.21,52.07 116.21,5.71 125.1,5.71 126.37,6.99 E3.10 127,6.35 v128.91,4.45 | v166.37,7.62 166.37,9.53 178.44,9.53 182.88,13.97 E5.3
  Bottom 0.33: v117.48,53.34 118.11,52.7 139.7,52.7 140.97,53.98 150.5,53.98 151.77,55.24 E17.5 | v166.37,7.62 163.2,4.45 v128.91,4.45
N$30  (via drill 0.61)
  Top 0.33: v148.59,39.37 148.59,53.34 149.86,54.61 E17.6
  Bottom 0.33: v148.59,39.37 149.23,38.73 182.25,38.73 184.79,36.2 E12.2
N$31  (via drill 0.61)
  Top 0.33: E16.12 132.72,47.62 133.99,47.62 E16.13 134.62,46.99 v134.62,44.45 | E5.6 174.63,14.61 172.72,12.7 161.29,12.7 161.29,24.13 158.75,26.67 v158.75,40.64 158.75,44.45 156.21,46.99 156.21,53.34 154.94,54.61 E17.4
  Bottom 0.33: v134.62,44.45 138.43,40.64 v158.75,40.64
N$32  (via drill 0.61)
  Top 0.33: v62.87,41.91 62.87,42.55 58.42,46.99 E13.13 | v127,42.55 127,46.99 E16.10
  Bottom 0.33: v62.87,41.91 63.5,42.55 v127,42.55
N$33
  Bottom 0.33: R9.2 133.99,20.32 132.72,20.32 C20.1 131.45,20.32 128.27,20.32 128.27,13.97 128.91,13.34 135.26,13.34 136.53,14.61 E3.1
N$34
  Top 0.33: 34.93,31.11 37.47,28.57 E6.13 | 34.93,31.11 31.12,34.92 E6.5 | 34.93,31.11 38.1,34.29 E6.2
N$35
  Top 0.33: E3.3 132.72,14.61 133.99,14.61 E3.2
N$36  (via drill 0.61)
  Top 0.33: v153.67,17.14 158.12,17.14 158.75,16.51 158.75,13.97 160.66,12.06 176.53,12.06 176.53,22.86 180.34,26.67 E12.11
  Bottom 0.33: v153.67,17.14 131.45,17.14 130.18,15.88 E3.4
N$37
  Bottom 0.33: E10.6 125.1,34.92 127,33.02 177.8,33.02 179.71,34.92 E12.4
N$38  (via drill 0.61)
  Top 0.33: R6.1 53.98,19.05 62.23,19.05 62.23,19.68 63.5,20.95 R8.1 | v102.24,24.13 102.24,20.95 106.68,16.51 E2.3
  Bottom 0.33: v102.24,24.13 71.12,24.13 68.58,21.59 64.14,21.59 R8.1
N$39  (via drill 0.61)
  Top 0.33: C19.1 51.44,19.05 53.34,20.95 R8.2 | v120.65,21.59 126.37,15.88 E3.5
  Bottom 0.33: v120.65,21.59 71.76,21.59 70.49,20.32 55.25,20.32 53.98,21.59 R8.2
N$40
  Top 0.33: E3.9 124.46,8.89 124.46,13.97 E3.6
N$41  (via drill 0.61)
  Top 0.33: v133.35,45.09 133.35,33.02 129.54,29.21 E10.11 | v149.86,45.09 149.86,46.99 E17.9
  Bottom 0.33: v133.35,45.09 133.99,45.72 149.86,45.72 | 149.86,45.72 179.71,45.72 180.34,46.35 180.34,46.99 E18.11 | 149.86,45.72 v149.86,45.09
N$42
  Top 0.33: 51.44,41.27 48.26,44.45 48.26,46.99 E13.9 | 51.44,41.27 55.88,36.83 E7.3 | 51.44,41.27 57.15,46.99 57.15,53.34 58.42,54.61 E13.2
N$43
  Top 0.33: E13.8 45.72,49.53 50.8,54.61 E13.5
  Bottom 0.33: E13.1 60.33,55.24 59.06,53.98 52.71,53.98 51.44,55.24 E13.5
N$44
  Bottom 0.33: E13.4 53.98,55.24 55.25,55.24 E13.3
N$45  (via drill 0.61)
  Top 0.33: 139.7,51.44 142.24,48.9 142.24,5.71 147.96,5.71 149.23,6.99 E4.9 | 139.7,51.44 125.1,51.44 125.1,48.9 E16.9 124.46,46.99 124.46,41.91 129.54,36.83 E10.4 | 139.7,51.44 v146.69,58.42
  Bottom 0.33: E13.10 51.44,48.9 53.34,50.8 121.92,50.8 123.83,48.9 E16.9 | v146.69,58.42 185.42,58.42 187.33,56.52 E18.1
N$46
  Top 0.33: E10.8 121.92,29.21 118.75,32.38 118.75,47.62 125.73,54.61 125.73,57.15 129.54,60.96 182.88,60.96 182.88,57.15 E18.3
N$47
  Top 0.33: E4.1 162.56,16.51 161.93,17.14 161.93,26.04 161.29,26.67 161.29,33.02 160.02,34.29 E11.2
N$48
  Top 0.33: E14.11 78.74,49.53 81.92,52.7 81.92,53.98 82.55,54.61 82.55,57.15 83.19,57.78 101.6,57.78 101.6,57.15 E15.5 102.24,55.24 103.51,55.24 E15.4
  Bottom 0.33: E18.8 172.09,47.62 170.82,46.35 106.05,46.35 105.41,45.72 85.09,45.72 84.46,46.35 80.65,46.35 79.38,47.62 E14.11
N$49
  Top 0.33: E17.3 157.48,57.15 158.12,57.78 158.12,58.42 179.07,58.42 179.07,53.34 182.88,49.53 E18.12
N$50  (via drill 0.61)
  Top 0.33: 158.12,52.7 157.48,52.07 157.48,50.8 159.39,48.9 E17.13 | 158.12,52.7 158.75,53.34 158.75,57.78 160.66,57.78 161.93,56.52 E17.1 | 158.12,52.7 156.21,54.61 v156.21,59.69 | v121.29,59.69 111.76,50.16 106.68,50.16 106.68,49.53 E15.12
  Bottom 0.33: E17.13 160.66,48.9 162.56,50.8 175.26,50.8 177.17,48.9 E18.10 | E14.10 76.84,48.9 78.11,50.16 87,50.16 87.63,49.53 87.63,46.35 104.78,46.35 106.05,47.62 E15.12 | v121.29,59.69 v156.21,59.69
N$51  (via drill 0.61)
  Top 0.33: v135.89,50.16 135.89,38.1 134.62,36.83 E10.2
  Bottom 0.33: v135.89,50.16 136.53,50.8 144.78,50.8 146.69,48.9 E17.8
N$52  (via drill 0.61)
  Top 0.33: 160.02,53.98 163.2,53.98 163.83,54.61 163.83,57.78 173.36,57.78 173.99,57.15 173.99,30.48 172.72,29.21 E12.8 | 160.02,53.98 160.02,54.61 E17.2 | v82.55,40.01 82.55,45.72 81.28,46.99 E14.12 | v123.19,38.73 123.19,50.8 127,54.61 E16.5 127.64,55.24 128.91,55.24 E16.4 129.54,57.15 129.54,59.69 148.59,59.69 151.13,57.15 151.13,50.8 152.4,49.53 E17.10 | 160.02,53.98 159.39,53.34 159.39,52.07 v158.75,51.44
  Bottom 0.33: v82.55,40.01 83.82,38.73 v123.19,38.73 | v158.75,51.44 157.48,50.16 154.31,50.16 153.04,48.9 E17.10
N$53  (via drill 0.61)
  Top 0.33: v165.1,36.2 170.18,31.11 v170.18,27.94
  Bottom 0.33: v165.1,36.2 163.83,37.47 133.99,37.47 132.72,36.2 E10.3 | v170.18,27.94 172.09,26.04 175.9,26.04 177.17,27.3 E12.10
N$54  (via drill 0.61)
  Top 0.33: v137.16,20.32 137.16,25.4 135.89,26.67 135.89,33.02 137.16,34.29 E10.1
  Bottom 0.33: v137.16,20.32 139.7,17.78 152.4,17.78 153.04,18.41 154.31,18.41 156.85,15.88 E4.3 158.12,14.61 160.02,12.7 177.8,12.7 182.25,8.26 E5.12
N$55
  Top 0.33: R10.2 96.52,4.45 96.52,6.35 E2.8
  Bottom 0.33: E12.12 182.88,26.67 191.77,17.78 191.77,3.17 96.52,3.17 R10.2
N$56
  Top 0.33: 131.45,3.81 131.45,6.99 E3.12 | 131.45,3.81 131.45,1.91 107.32,1.91 102.24,6.99 E2.10 | 131.45,3.81 177.8,3.81 180.34,6.35 E5.11
N$57
  Top 0.33: E2.9 99.06,8.89 101.6,11.43 101.6,13.97 E2.5 102.24,14.61 103.51,14.61 E2.4
  Bottom 0.33: E5.9 174.63,8.26 172.72,10.16 101.6,10.16 99.7,8.26 E2.9
N$58
  Top 0.33: E4.11 155.58,6.99 157.48,5.08 176.53,5.08 177.8,6.35 E5.10
N$60
  Top 0.33: E4.2 160.02,16.51 156.21,20.32 156.21,45.72 154.94,46.99 E17.11
N$61  (via drill 0.61)
  Top 0.33: v83.82,45.09 83.82,46.99 E14.13 | v107.95,45.09 109.22,46.35 109.22,46.99 E15.13
  Bottom 0.33: v83.82,45.09 v107.95,45.09
VCC
  Top 0.33: 64.77,22.86 64.77,20.95 63.5,19.68 R6.2 | 64.77,22.86 60.96,26.67 E7.14 | 64.77,22.86 64.77,43.18 60.96,46.99 E13.14 | E6.14 40.64,26.67 41.91,25.4 41.91,9.53 38.1,5.71 R3.2 | 184.15,20.32 185.42,21.59 185.42,26.67 E12.13 186.06,27.3 187.33,27.3 E12.14 | 184.15,20.32 180.34,16.51 E5.4 | 184.15,20.32 184.15,10.16 185.42,8.89 E5.13 | E18.4 180.34,54.61 185.42,49.53 E18.13 | E17.14 162.56,46.99 163.83,45.72 163.83,31.11 165.1,29.84 C10.1 | E18.14 187.96,46.99 187.96,36.83 E12.1 | R10.1 86.36,4.45 88.9,6.99 88.9,8.26 C1.1 88.9,9.53 87.63,10.79 87.63,31.11 | 87.63,48.9 88.27,48.9 88.27,49.53 C13.1 | 87.63,48.9 87,48.9 E14.14 | 87.63,31.11 88.9,29.84 C7.1 | 87.63,31.11 87.63,48.9 | E16.14 137.16,46.99 137.16,46.35 139.7,43.81 R5.2 139.7,42.55 138.43,41.27 138.43,31.11 139.7,29.84 C9.1 | R7.2 145.42,22.86 146.69,22.86 R4.1 147.32,23.5 147.32,26.67 E11.8 | 113.03,25.4 111.76,26.67 E9.14 | 113.03,25.4 113.03,10.79 114.3,9.53 C2.1 | 113.03,25.4 113.03,45.72 111.76,46.99 E15.14 | E10.14 137.16,26.67 138.43,25.4 138.43,10.79 139.7,9.53 C3.1
  Bottom 0.33: E13.14 61.6,48.9 62.23,49.53 62.87,49.53 C12.1 | E6.14 41.28,27.3 42.55,26.04 59.06,26.04 60.33,27.3 E7.14 61.6,28.57 62.23,28.57 62.87,29.21 C6.1 | U$2.A2 13.97,4.45 22.23,4.45 18.+ 23.5,5.71 24.13,6.35 36.2,6.35 37.47,5.08 R3.2 38.74,5.08 40.64,6.99 70.49,6.99 E1.8 71.76,6.99 74.3,4.45 86.36,4.45 R10.1 | C5.1 189.87,8.89 189.23,8.26 188.6,8.26 E5.14 187.33,6.99 186.06,6.99 E5.13 184.79,6.99 183.52,5.71 170.18,5.71 167.01,8.89 165.74,8.89 C4.1 164.47,8.89 163.83,8.89 163.2,8.26 E4.14 161.93,8.26 160.66,9.53 139.7,9.53 | E18.13 186.06,47.62 187.33,47.62 E18.14 188.6,48.9 189.23,48.9 189.87,49.53 C17.1 | E17.14 163.2,48.9 163.83,49.53 164.47,49.53 C16.1 | 187.96,29.84 190.5,29.84 C11.1 | 187.96,29.84 166.37,29.84 165.74,29.21 C10.1 | 187.96,29.84 187.96,34.29 E12.1 | 187.96,29.84 187.96,29.21 E12.14 | E8.14 87,28.57 87.63,29.21 88.27,29.21 C7.1 | C15.1 139.07,49.53 138.43,48.9 137.8,48.9 E16.14 | E10.14 137.8,28.57 138.43,29.21 139.07,29.21 C9.1 140.34,29.21 140.97,28.57 146.69,28.57 E11.8 | E15.14 112.4,48.9 113.03,49.53 113.67,49.53 C14.1 114.3,50.16 90.17,50.16 89.54,49.53 C13.1 | E9.14 112.4,28.57 113.03,29.21 113.67,29.21 C8.1 | E2.14 112.4,8.26 113.03,8.89 113.67,8.89 C2.1 114.94,8.89 115.57,9.53 139.7,9.53 | E3.14 137.8,8.26 138.43,8.89 139.07,8.89 C3.1 | 139.7,9.53 C3.1 | 139.7,9.53 C3.1
VECTOR_BIT_02_H  (via drill 0.61)
  Top 0.33: v31.12,30.48 31.75,29.84 v31.75,10.16 | v18.42,8.89 15.24,12.06 v15.24,12.7
  Bottom 0.33: v31.12,30.48 48.26,30.48 48.9,31.11 103.51,31.11 106.05,28.57 E9.12 | v31.75,10.16 30.48,8.89 v18.42,8.89 | v15.24,12.7 13.97,12.7 U$2.D2

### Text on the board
Top: M7821 Interrupt Control
Bottom: M7821 Interrupt Control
